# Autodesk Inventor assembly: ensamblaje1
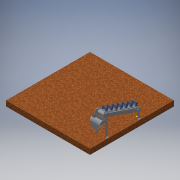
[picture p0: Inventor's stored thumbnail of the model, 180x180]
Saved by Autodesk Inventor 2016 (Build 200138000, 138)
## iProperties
Created: 2016-06
Part Number: ensamblaje1
Document SubType Name: Assembly
Designer: yesi alvarez
Mass: 32615.5 g
Surface Area: 17323.4 cm^2
Volume: 32615.5 cm^3
Density: 1 g/cm^3
Author: yesi alvarez
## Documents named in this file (11)
- C:\Users\miguel alvarez\Desktop\proyecto del profe. valcarcel\ensamblaje1.iam
- C:\Users\miguel alvarez\Desktop\proyecto del profe. valcarcel\tablero.ipt
- C:\Users\miguel alvarez\Desktop\proyecto del profe. valcarcel\soporte1.ipt
- C:\Users\miguel alvarez\Desktop\proyecto del profe. valcarcel\pieza que une los rodillos.ipt
- C:\Users\miguel alvarez\Desktop\proyecto del profe. valcarcel\soporte2.ipt
- C:\Users\miguel alvarez\Desktop\proyecto del profe. valcarcel\rodillo.ipt
- C:\Users\miguel alvarez\Desktop\proyecto del profe. valcarcel\ensamblaje1\Design Accelerator\Bolted Connection3.iam
- C:\Users\miguel alvarez\Desktop\proyecto del profe. valcarcel\tuerca.ipt
- C:\Users\miguel alvarez\Desktop\proyecto del profe. valcarcel\faja2.ipt
- C:\Users\miguel alvarez\Desktop\Alvarez\cangilogeno.ipt
- C:\Users\miguel alvarez\Desktop\proyecto del profe. valcarcel\recepcion2.ipt
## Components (42 placed, 10 different names)
1. tablero:1 — Mate:1, Mate:4, Mate:16, Mate:19, Mate:66, Mate:67, Mate:68, Mate:69, Flush:3
2. soporte1:1 — Mate:1, Mate:2, Mate:3, Mate:20, Mate:21, Mate:22, Mate:23, Mate:44, Mate:45, Mate:46, Mate:57, Flush:2, Mate:68
3. soporte1:2 — Mate:17, Mate:18, Mate:19, Mate:42, Mate:43, Mate:49, Mate:50, Mate:55, Mate:56, Flush:2, Mate:69
4. pieza que une los rodillos:1 — Mate:2, Mate:3, Mate:5, Mate:6, Mate:7, Mate:8, Mate:9, Mate:10, Mate:11, Mate:24, Mate:25, Mate:26, Mate:27, Mate:28, Mate:29, Mate:61
5. pieza que une los rodillos:2 — Mate:12, Mate:13, Mate:14, Mate:15, Mate:17, Mate:18, Mate:34, Mate:35, Mate:38, Mate:39, Mate:40, Mate:41, Mate:60, Mate:62, Mate:63, Mate:64, Mate:65
6. soporte2:1 — Mate:4, Mate:5, Mate:6, Mate:30, Mate:31, Mate:47, Mate:48, Mate:58, Mate:59, Flush:1, Mate:66, Mate:86, Tangent:2
7. soporte2:2 — Mate:14, Mate:15, Mate:16, Mate:32, Mate:33, Mate:51, Mate:52, Mate:53, Mate:54, Flush:1, Mate:67, Flush:3, Mate:84, Mate:85
8. rodillo:1 — Mate:7, Mate:13, Mate:65, Flush:4, Flush:12
9. rodillo:2 — Mate:8, Mate:64, Tangent:1
10. rodillo:3 — Mate:11, Mate:12, Mate:61, Mate:62, Insert:1
11. rodillo:4 — Mate:10, Mate:60
12. rodillo:5 — Mate:9, Mate:63
13. Bolted Connection:1 [sub-assembly] — Mate:20, Mate:21
14. tuerca:1 — Mate:28, Mate:29
15. tuerca:2 — Mate:26, Mate:27
16. tuerca:3 — Mate:24, Mate:25
17. tuerca:4 — Mate:22, Mate:23
18. tuerca:5 — Mate:30, Mate:31
19. tuerca:6 — Mate:34, Mate:39
20. tuerca:7 — Mate:38, Mate:41
21. tuerca:8 — Mate:32, Mate:33
22. tuerca:9 — Mate:42, Mate:43
23. tuerca:10 — Mate:35, Mate:40
24. tuerca:11 — Mate:49, Mate:55
25. tuerca:12 — Mate:52, Mate:53
26. tuerca:13 — Mate:46, Mate:57
27. tuerca:14 — Mate:48, Mate:58
28. tuerca:15 — Mate:51, Mate:54
29. tuerca:16 — Mate:44, Mate:45
30. tuerca:17 — Mate:47, Mate:59
31. tuerca:18 — Mate:50, Mate:56
32. faja2:1 — Insert:1, Flush:4, Mate:70, Mate:71, Flush:5, Mate:72, Mate:73, Mate:74, Mate:75, Mate:76, Flush:6, Flush:7, Flush:8, Flush:9, Flush:10, Mate:77, Mate:78, Mate:79, Mate:80, Mate:81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
33. cangilogeno:1 — Mate:70, Mate:71, Flush:5
34. cangilogeno:2 — Mate:73, Flush:7, Mate:78
35. cangilogeno:3 — Mate:82, Mate:83, Flush:11
36. cangilogeno:4 — Mate:74, Flush:8, Mate:79
37. cangilogeno:5 — Mate:75, Flush:9, Mate:80
38. cangilogeno:6 — Mate:72, Flush:6, Mate:77
39. cangilogeno:7 — Mate:76, Flush:10, Mate:81
40. recepcion2:1 — Mate:84, Mate:85, Mate:86, Mate:87, Insert:2
41. tuerca:19 — Mate:87, Tangent:2
42. tuerca:20 — Insert:2
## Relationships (101: Mate 85, Flush 12, Insert 2, Tangent 2)
- Mate:1: tablero:1 ↔ soporte1:1
- Mate:2: soporte1:1 ↔ pieza que une los rodillos:1
- Mate:3: soporte1:1 ↔ pieza que une los rodillos:1
- Mate:4: tablero:1 ↔ soporte2:1
- Mate:5: pieza que une los rodillos:1 ↔ soporte2:1
- Mate:6: pieza que une los rodillos:1 ↔ soporte2:1
- Mate:7: pieza que une los rodillos:1 ↔ rodillo:1
- Mate:8: pieza que une los rodillos:1 ↔ rodillo:2
- Mate:9: pieza que une los rodillos:1 ↔ rodillo:5
- Mate:10: pieza que une los rodillos:1 ↔ rodillo:4
- Mate:11: pieza que une los rodillos:1 ↔ rodillo:3
- Mate:12: pieza que une los rodillos:2 ↔ rodillo:3
- Mate:13: pieza que une los rodillos:2 ↔ rodillo:1
- Mate:14: pieza que une los rodillos:2 ↔ soporte2:2
- Mate:15: pieza que une los rodillos:2 ↔ soporte2:2
- Mate:16: tablero:1 ↔ soporte2:2
- Mate:17: soporte1:2 ↔ pieza que une los rodillos:2
- Mate:18: soporte1:2 ↔ pieza que une los rodillos:2
- Mate:19: tablero:1 ↔ soporte1:2
- Mate:20: soporte1:1 ↔ Bolted Connection:1
- Mate:21: soporte1:1 ↔ Bolted Connection:1
- Mate:22: soporte1:1 ↔ tuerca:4
- Mate:23: soporte1:1 ↔ tuerca:4
- Mate:24: pieza que une los rodillos:1 ↔ tuerca:3
- Mate:25: pieza que une los rodillos:1 ↔ tuerca:3
- Mate:26: pieza que une los rodillos:1 ↔ tuerca:2
- Mate:27: pieza que une los rodillos:1 ↔ tuerca:2
- Mate:28: pieza que une los rodillos:1 ↔ tuerca:1
- Mate:29: pieza que une los rodillos:1 ↔ tuerca:1
- Mate:30: soporte2:1 ↔ tuerca:5
- Mate:31: soporte2:1 ↔ tuerca:5
- Mate:32: soporte2:2 ↔ tuerca:8
- Mate:33: soporte2:2 ↔ tuerca:8
- Mate:34: pieza que une los rodillos:2 ↔ tuerca:6
- Mate:35: pieza que une los rodillos:2 ↔ tuerca:10
- Mate:38: pieza que une los rodillos:2 ↔ tuerca:7
- Mate:39: pieza que une los rodillos:2 ↔ tuerca:6
- Mate:40: pieza que une los rodillos:2 ↔ tuerca:10
- Mate:41: pieza que une los rodillos:2 ↔ tuerca:7
- Mate:42: soporte1:2 ↔ tuerca:9
- Mate:43: soporte1:2 ↔ tuerca:9
- Mate:44: soporte1:1 ↔ tuerca:16
- Mate:45: soporte1:1 ↔ tuerca:16
- Mate:46: soporte1:1 ↔ tuerca:13
- Mate:47: soporte2:1 ↔ tuerca:17
- Mate:48: soporte2:1 ↔ tuerca:14
- Mate:49: soporte1:2 ↔ tuerca:11
- Mate:50: soporte1:2 ↔ tuerca:18
- Mate:51: soporte2:2 ↔ tuerca:15
- Mate:52: soporte2:2 ↔ tuerca:12
- Mate:53: soporte2:2 ↔ tuerca:12
- Mate:54: soporte2:2 ↔ tuerca:15
- Mate:55: soporte1:2 ↔ tuerca:11
- Mate:56: soporte1:2 ↔ tuerca:18
- Mate:57: soporte1:1 ↔ tuerca:13
- Mate:58: soporte2:1 ↔ tuerca:14
- Mate:59: soporte2:1 ↔ tuerca:17
- Mate:60: pieza que une los rodillos:2 ↔ rodillo:4
- Mate:61: pieza que une los rodillos:1 ↔ rodillo:3
- Mate:62: pieza que une los rodillos:2 ↔ rodillo:3
- Insert:1: rodillo:3 ↔ faja2:1
- Mate:63: pieza que une los rodillos:2 ↔ rodillo:5
- Mate:64: pieza que une los rodillos:2 ↔ rodillo:2
- Mate:65: pieza que une los rodillos:2 ↔ rodillo:1
- Flush:1: soporte2:1 ↔ soporte2:2
- Flush:2: soporte1:1 ↔ soporte1:2
- Mate:66: tablero:1 ↔ soporte2:1
- Mate:67: tablero:1 ↔ soporte2:2
- Mate:68: tablero:1 ↔ soporte1:1
- Mate:69: tablero:1 ↔ soporte1:2
- Flush:3: tablero:1 ↔ soporte2:2
- Flush:4: rodillo:1 ↔ faja2:1
- Mate:70: faja2:1 ↔ cangilogeno:1
- Mate:71: faja2:1 ↔ cangilogeno:1
- Flush:5: faja2:1 ↔ cangilogeno:1
- Mate:72: faja2:1 ↔ cangilogeno:6
- Mate:73: faja2:1 ↔ cangilogeno:2
- Mate:74: faja2:1 ↔ cangilogeno:4
- Mate:75: faja2:1 ↔ cangilogeno:5
- Mate:76: faja2:1 ↔ cangilogeno:7
- Flush:6: faja2:1 ↔ cangilogeno:6
- Flush:7: faja2:1 ↔ cangilogeno:2
- Flush:8: faja2:1 ↔ cangilogeno:4
- Flush:9: faja2:1 ↔ cangilogeno:5
- Flush:10: faja2:1 ↔ cangilogeno:7
- Mate:77: faja2:1 ↔ cangilogeno:6
- Mate:78: faja2:1 ↔ cangilogeno:2
- Mate:79: faja2:1 ↔ cangilogeno:4
- Mate:80: faja2:1 ↔ cangilogeno:5
- Mate:81: faja2:1 ↔ cangilogeno:7
- Mate:82: faja2:1 ↔ cangilogeno:3
- Mate:83: faja2:1 ↔ cangilogeno:3
- Flush:11: faja2:1 ↔ cangilogeno:3
- Flush:12: rodillo:1 ↔ faja2:1
- Tangent:1: rodillo:2 ↔ faja2:1
- Mate:84: soporte2:2 ↔ recepcion2:1
- Mate:85: soporte2:2 ↔ recepcion2:1
- Mate:86: soporte2:1 ↔ recepcion2:1
- Mate:87: recepcion2:1 ↔ tuerca:19
- Tangent:2: soporte2:1 ↔ tuerca:19
- Insert:2: recepcion2:1 ↔ tuerca:20
